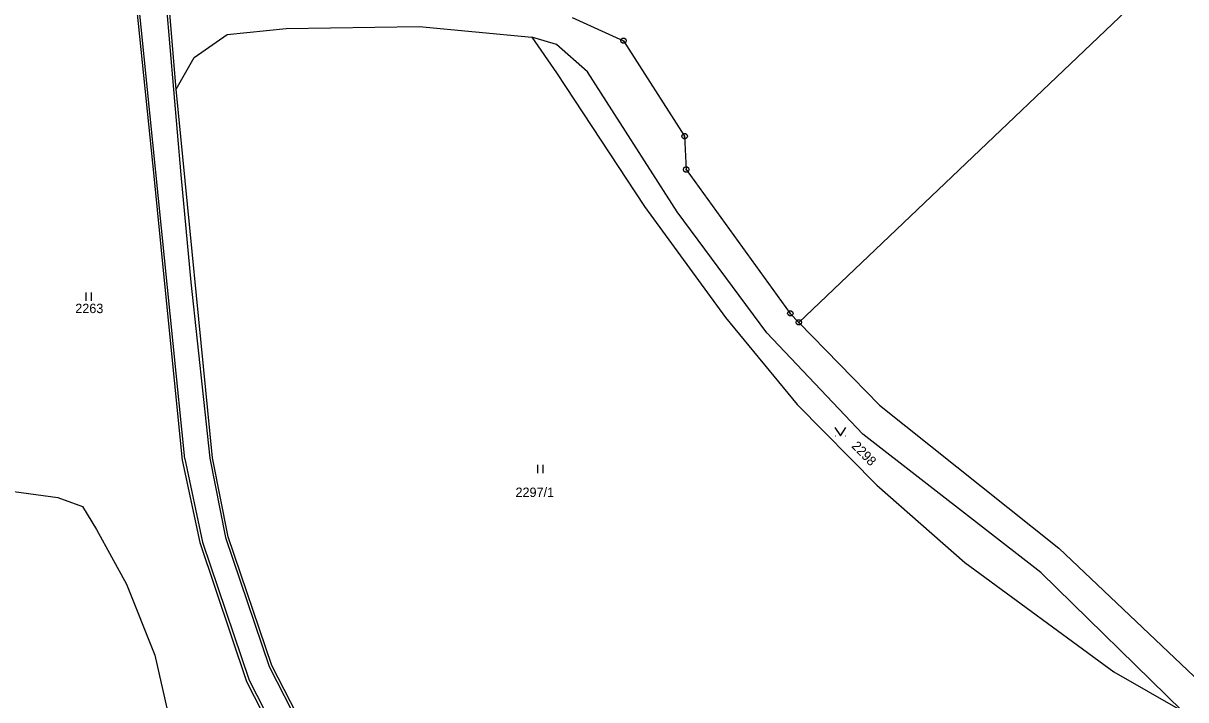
# Model space of a CAD drawing. Extents: x -609861 to -605046, y -1120287 to -1116307.
# Drawn here: x -606146.8 to -605937.2, y -1118420 to -1118298.1 of the extents above; entities that cross this region are included whole.
import ezdxf

# ---------------------------------------------------------------- set-up
doc = ezdxf.new("R2010")
doc.units = 0
for name, color, linetype in [('Vrstva 1', 7, 'Continuous'), ('Vrstva 2', 7, 'Continuous'), ('Vrstva 3', 7, 'Continuous'), ('Vrstva 4', 7, 'Continuous'), ('Vrstva 8', 7, 'Continuous')]:
    doc.layers.add(name, color=color, linetype=linetype)

msp = doc.modelspace()

# ---------------------------------------------------------------- linework, layer by layer
at = {"layer": 'Vrstva 1'}
for p, q in [((-605927.43, -1118276.3), (-606006.94, -1118352.01)), ((-606119.29, -1118309.96), (-606120.91, -1118289.88)), ((-606126.61, -1118293.25), (-606123.29, -1118325.64)), ((-606047.81, -1118297.03), (-606038.57, -1118301.21)), ((-606110.09, -1118300.09), (-606099.4, -1118298.98)), ((-606099.4, -1118298.98), (-606075.42, -1118298.63)), ((-606075.42, -1118298.63), (-606055.09, -1118300.56)), ((-606116.01, -1118304.25), (-606110.09, -1118300.09)), ((-606050.68, -1118301.89), (-606055.09, -1118300.56)), ((-606055.09, -1118300.56), (-606050.64, -1118306.98)), ((-606045.09, -1118306.8), (-606050.68, -1118301.89)), ((-606038.57, -1118301.21), (-606027.55, -1118318.44)), ((-606119.29, -1118309.96), (-606116.01, -1118304.25)), ((-606050.64, -1118306.98), (-606034.79, -1118331.12)), ((-606028.92, -1118332.06), (-606045.09, -1118306.8)), ((-606112.72, -1118376.4), (-606119.29, -1118309.96)), ((-606027.55, -1118318.44), (-606027.27, -1118324.43)), ((-606027.27, -1118324.43), (-606008.49, -1118350.37)), ((-606123.29, -1118325.64), (-606121.42, -1118344.45)), ((-606034.79, -1118331.12), (-606020.15, -1118351.14)), ((-606012.71, -1118353.91), (-606028.92, -1118332.06)), ((-606121.42, -1118344.45), (-606118.19, -1118376.82)), ((-606020.15, -1118351.14), (-606007.25, -1118366.83)), ((-606008.49, -1118350.37), (-606006.94, -1118352.01)), ((-606006.94, -1118352.01), (-605992.41, -1118366.94)), ((-605995.43, -1118372.17), (-606012.71, -1118353.91)), ((-606007.25, -1118366.83), (-605992.89, -1118381.34)), ((-605992.41, -1118366.94), (-605960.05, -1118392.69)), ((-605963.32, -1118397.11), (-605995.43, -1118372.17)), ((-606118.19, -1118376.82), (-606115.01, -1118391.7)), ((-606109.86, -1118390.66), (-606112.72, -1118376.4)), ((-605992.89, -1118381.34), (-605976.98, -1118395.28)), ((-606149.9, -1118382.31), (-606140.64, -1118383.59)), ((-606140.64, -1118383.59), (-606136.18, -1118385.18)), ((-606136.18, -1118385.18), (-606133.63, -1118389.33)), ((-606133.63, -1118389.33), (-606128.2, -1118399.23)), ((-606115.01, -1118391.7), (-606106.58, -1118416.73)), ((-606102.03, -1118413.85), (-606109.86, -1118390.66)), ((-605960.05, -1118392.69), (-605933.33, -1118418)), ((-605976.98, -1118395.28), (-605950.13, -1118415.01)), ((-605937.74, -1118422.09), (-605963.32, -1118397.11)), ((-606128.2, -1118399.23), (-606123.1, -1118412)), ((-606123.1, -1118412), (-606120.62, -1118422.86)), ((-606090.37, -1118436.49), (-606102.03, -1118413.85)), ((-605950.13, -1118415.01), (-605937.74, -1118422.09)), ((-606106.58, -1118416.73), (-606097.03, -1118435.46))]:
    msp.add_line(p, q, dxfattribs=at)
at = {"layer": 'Vrstva 3'}
for p, q in [((-606135.56, -1118346.63), (-606135.56, -1118348.13)), ((-606134.56, -1118348.13), (-606134.56, -1118346.63)), ((-606000.41, -1118372.45), (-606000.31, -1118372.45)), ((-605998.61, -1118372.45), (-605998.51, -1118372.45)), ((-606054.06, -1118377.7), (-606054.06, -1118379.2)), ((-606053.06, -1118379.2), (-606053.06, -1118377.7))]:
    msp.add_line(p, q, dxfattribs=at)
msp.add_lwpolyline([(-606000.46, -1118370.95), (-605999.46, -1118372.45), (-605998.46, -1118370.95)], dxfattribs=at)
at = {"layer": 'Vrstva 4'}
for p, q in [((-606117.71, -1118376.58), (-606126.11, -1118293.2)), ((-606121.04, -1118294.64), (-606118.45, -1118325.38)), ((-606118.45, -1118325.38), (-606116.6, -1118344.76)), ((-606116.6, -1118344.76), (-606113.21, -1118376.48)), ((-606117.71, -1118376.58), (-606114.53, -1118391.65)), ((-606113.21, -1118376.48), (-606110.34, -1118390.79)), ((-606114.53, -1118391.65), (-606106.12, -1118416.53)), ((-606110.34, -1118390.79), (-606102.49, -1118414.05)), ((-606102.49, -1118414.05), (-606090.8, -1118436.74)), ((-606106.12, -1118416.53), (-606093.57, -1118440.71))]:
    msp.add_line(p, q, dxfattribs=at)
at = {"layer": 'Vrstva 8'}
for p, q in [((-606038.69, -1118301.21), (-606038.45, -1118301.21)), ((-606027.67, -1118318.44), (-606027.43, -1118318.44)), ((-606027.39, -1118324.43), (-606027.15, -1118324.43)), ((-606008.61, -1118350.37), (-606008.37, -1118350.37)), ((-606007.06, -1118352.01), (-606006.82, -1118352.01))]:
    msp.add_line(p, q, dxfattribs=at)
for points in [[(-606038.42, -1118300.73), (-606038.17, -1118300.91), (-606038.07, -1118301.2), (-606038.17, -1118301.49), (-606038.42, -1118301.67), (-606038.73, -1118301.67), (-606038.98, -1118301.49), (-606039.08, -1118301.2), (-606038.98, -1118300.91), (-606038.73, -1118300.73)], [(-606027.4, -1118317.96), (-606027.15, -1118318.14), (-606027.05, -1118318.43), (-606027.15, -1118318.72), (-606027.4, -1118318.9), (-606027.71, -1118318.9), (-606027.96, -1118318.72), (-606028.06, -1118318.43), (-606027.96, -1118318.14), (-606027.71, -1118317.96)], [(-606027.12, -1118323.95), (-606026.87, -1118324.13), (-606026.77, -1118324.42), (-606026.87, -1118324.71), (-606027.12, -1118324.89), (-606027.43, -1118324.89), (-606027.68, -1118324.71), (-606027.78, -1118324.42), (-606027.68, -1118324.13), (-606027.43, -1118323.95)], [(-606008.34, -1118349.89), (-606008.09, -1118350.07), (-606007.99, -1118350.36), (-606008.09, -1118350.65), (-606008.34, -1118350.83), (-606008.65, -1118350.83), (-606008.9, -1118350.65), (-606009, -1118350.36), (-606008.9, -1118350.07), (-606008.65, -1118349.89)], [(-606006.79, -1118351.53), (-606006.54, -1118351.71), (-606006.44, -1118352), (-606006.54, -1118352.29), (-606006.79, -1118352.47), (-606007.1, -1118352.47), (-606007.35, -1118352.29), (-606007.45, -1118352), (-606007.35, -1118351.71), (-606007.1, -1118351.53)]]:
    msp.add_lwpolyline(points, close=True, dxfattribs=at)

# ---------------------------------------------------------------- texts
at = {"layer": 'Vrstva 2'}
for s, p in [('2263', (-606137.463, -1118350.33)), ('2297/1', (-606058.052, -1118383.49))]:
    msp.add_text(s, height=1.7, dxfattribs=at).set_placement(p)
msp.add_text('2298', height=1.7, rotation=314.32465, dxfattribs=at).set_placement((-605997.544, -1118374.41))

doc.saveas('drawing.dxf')
